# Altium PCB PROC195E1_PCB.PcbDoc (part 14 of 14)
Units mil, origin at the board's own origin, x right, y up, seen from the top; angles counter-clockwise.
Board outline 3110.24 x 2500 mil, 10 copper layers (Top Layer, L02_GND1, L03_SIG1, L04_GND2, L05_PWR1, L06_PWR2, L07_GND3, L08_SIG2, L09_GND4, Bottom Layer), stack 66.407 mil thick; 571 components, 538 nets, 6726 pads, 1286 vias.
Unrouted connection lines stored in the file: 4.
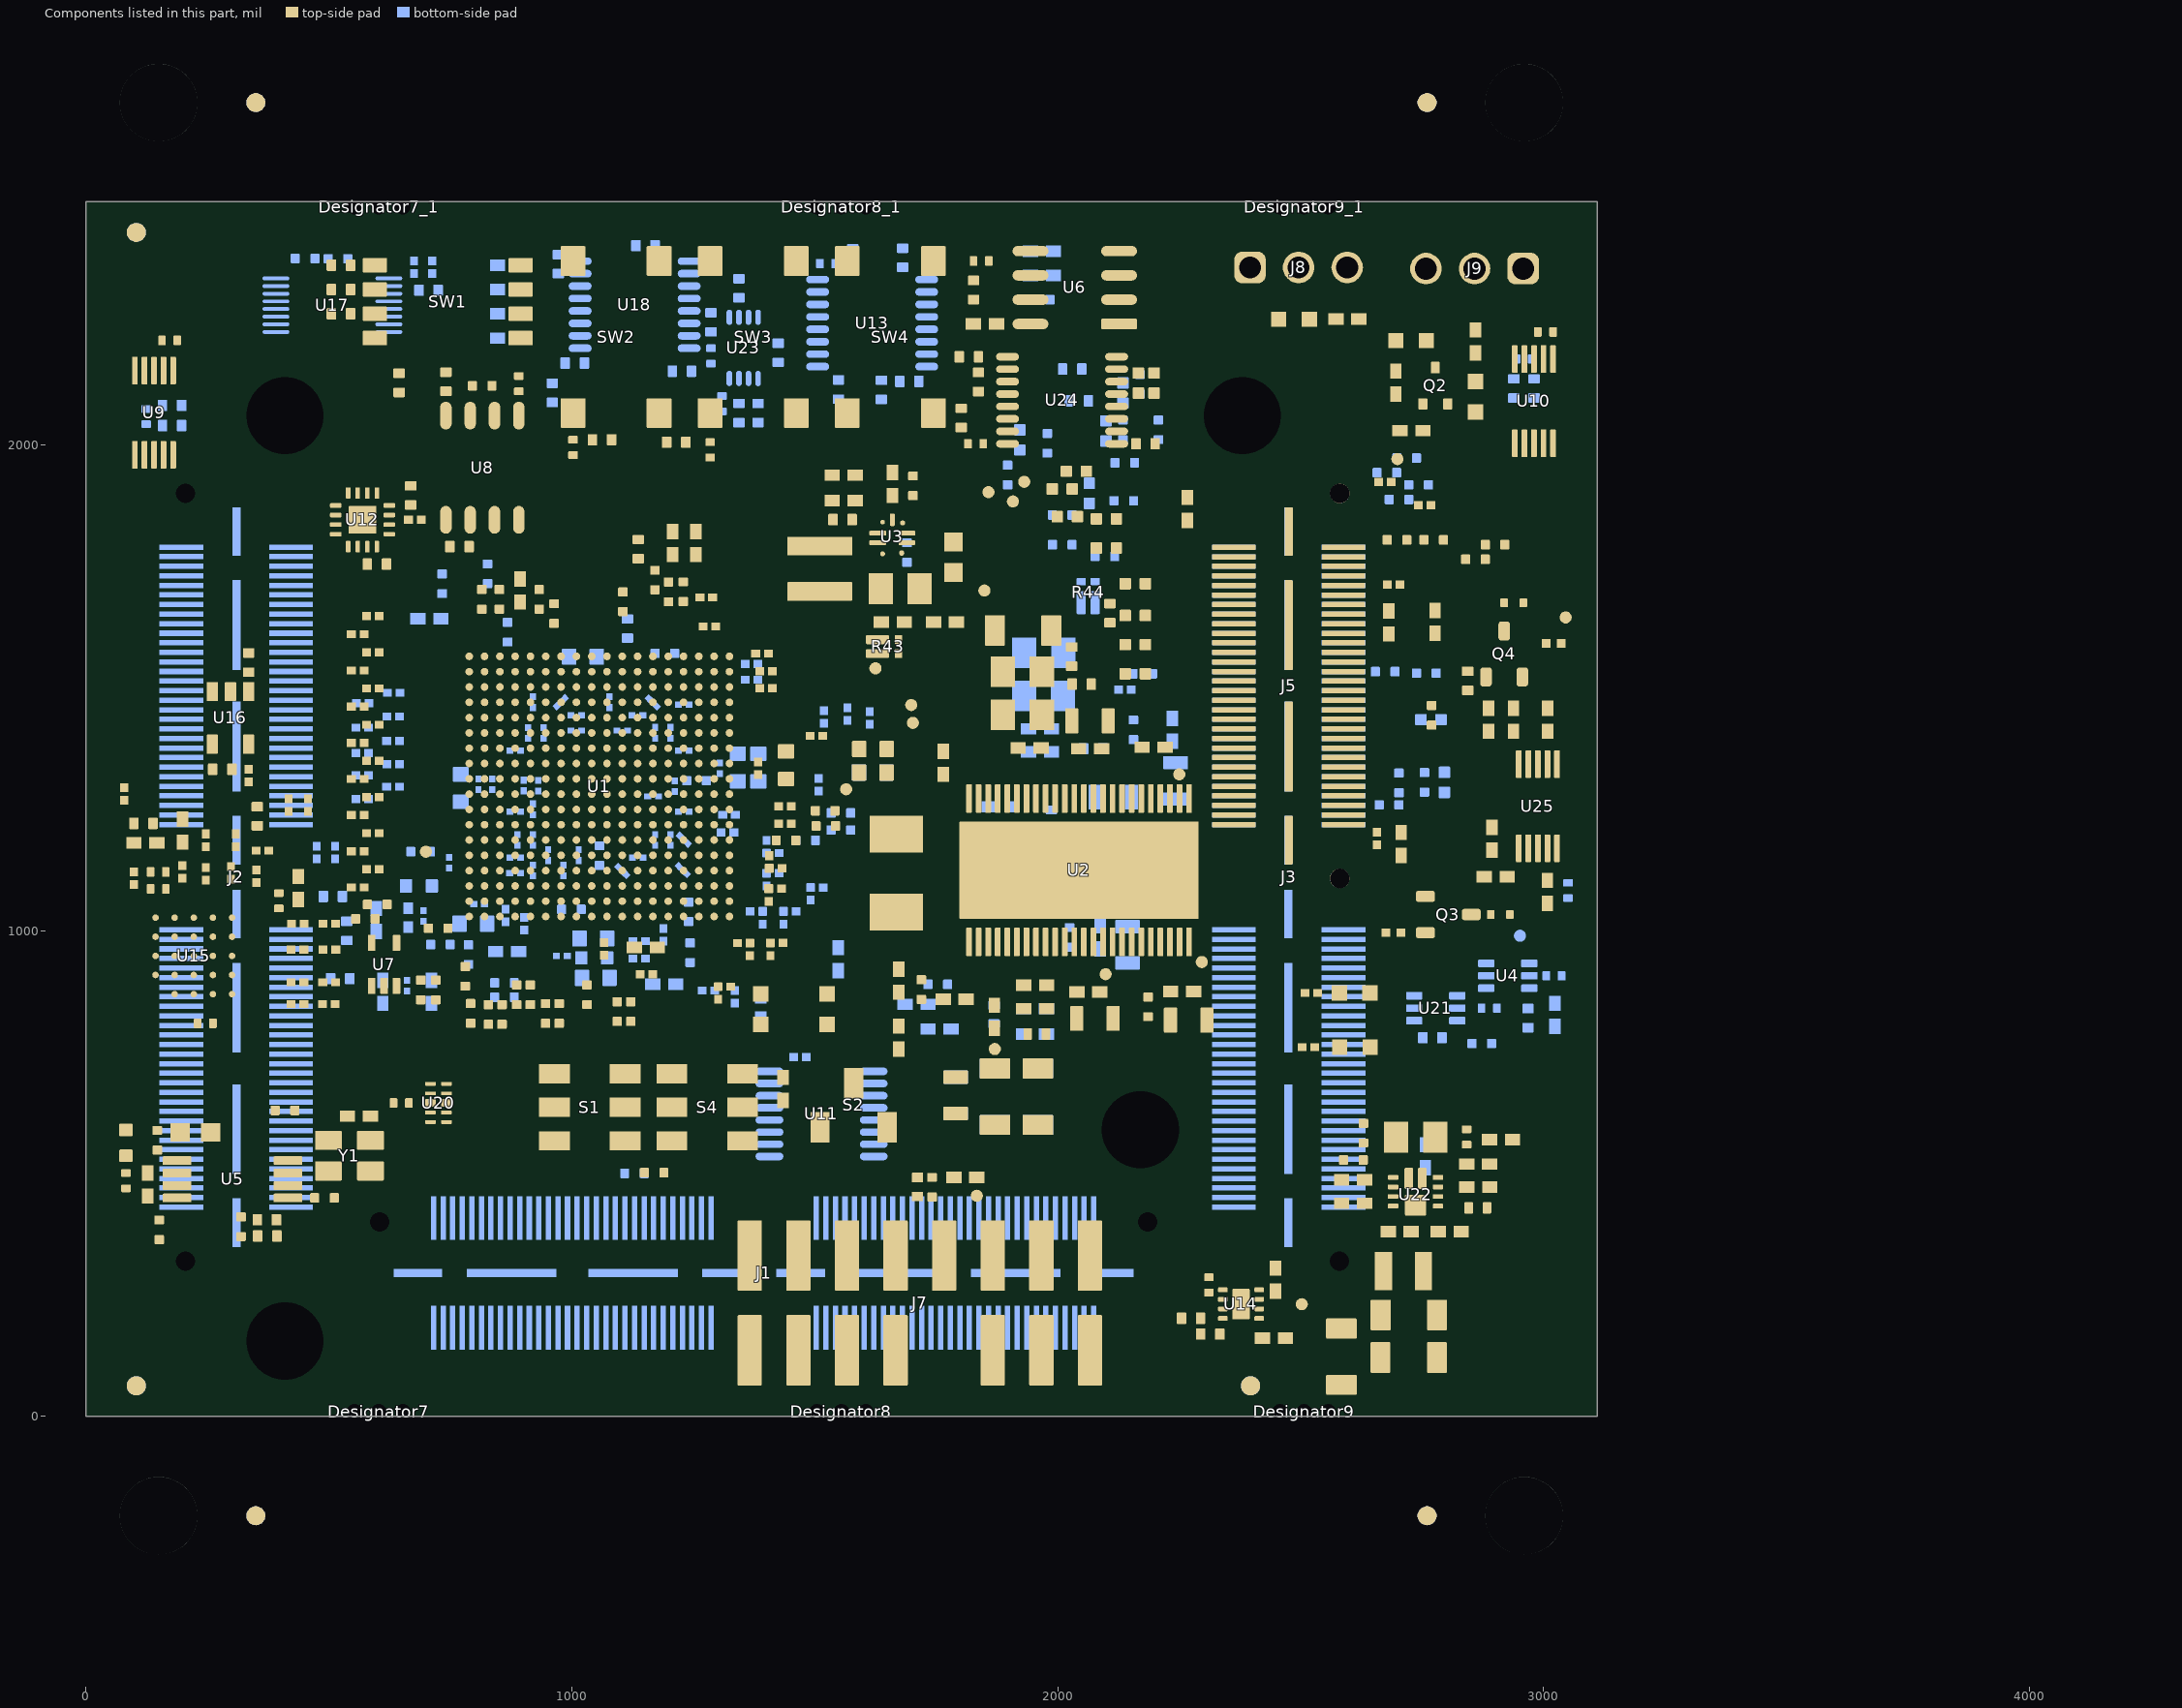
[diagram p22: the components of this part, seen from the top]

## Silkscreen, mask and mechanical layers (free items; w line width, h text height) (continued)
M10 Fab Notes:
  drawing of 181 lines, arcs and shapes, not listed
  text "DESIGN INFORMATION" at 11891.13,5008.92 h60
  text "3.2" at 12288,4885 h60
  text "MIN. TRACK WIDTH:" at 11246.57,4876.79 h60
  text "MIL" at 12497.57,4876.79 h60
  text "3.4" at 12290.75,4756.45 h60
  text "MIN. CLEARANCE:" at 11246.57,4752.67 h60
  text "MIL" at 12497.57,4752.67 h60
  text "MIN. VIA PAD SIZE:" at 11246.57,4628.54 h60
  text "18" at 12312.82,4628.54 h60
  text "MIL" at 12497.57,4628.54 h60
  text "0.05mm (2MIL)" at 11941.57,4498.64 h60
  text "MINIMUM ANNULAR RING" at 10917.34,4490.42 h60
  text "EXTERNAL" at 12649.57,4490.42 h60
  text "PER" at 11117.34,4380.29 h60
  text "IPC-D-275 CLASS 2 LEVEL C" at 11337.34,4380.29 h60
  text "MIL, HOLES" at 12825.57,4279.81 h60
  text "+/-" at 12433.11,4271.23 h60
  text "+/-" at 13287.11,4271.23 h60
  text "REGISTRATION TOLERANCES:" at 10917.34,4270.16 h60
  text "METAL" at 12117.11,4270.16 h60
  text "5" at 12693.31,4270.16 h60
  text "3" at 13526.31,4270.16 h60
  text "MIL" at 13642.57,4270.16 h60
  text "HOLE SIZE TOLERANCE (UNLESS OTHERWISE SPECIFIED):" at 10917.34,4171.85 h60
  text "+/-" at 13287.11,4168.97 h60
  text "3" at 13526.31,4167.91 h60
  text "MIL" at 13642.57,4167.91 h60
  text "MATERIAL:" at 10842.57,4030.26 h60
  text "FR-4 High Tg" at 11829.01,3901.74 h60
  text "X" at 11684.57,3893.75 h60
  text "FR-408" at 11263.57,3889.23 h60
  text "OTHER" at 12751.57,3889.23 h60
  text "70.4 MILS" at 13248.67,3756.2 h60
  text "62 MIL (1.6mm) +/-10%" at 11583.67,3746.2 h60
  text "X" at 12740,3740 h60
  text "THICKNESS:" at 10917.34,3737.98 h60
  text "OTHER" at 12868.57,3737.98 h60
  text "TOLERANCE:" at 10917.34,3599.67 h60
  text "X" at 11765.57,3599.67 h60
  text "ANSI IPC-6012 TYPE 3 CLASS 2" at 11943.58,3599.67 h60
  text "OTHER +/-" at 11943.57,3455.48 h60
  text "BOW & TWIST:" at 10917.34,3310.29 h60
  text "X" at 11765.57,3310.29 h60
  text "ANSI IPC-6012 TYPE 3 CLASS 2" at 11943.58,3310.29 h60
  text "SCALE : NTS" at 4511.09,3292.46 h80
  text "NOTES:" at 3394.07,3218.65 h60
  text "OTHER +/-" at 11943.57,3163.59 h60
  text "1. BOARD SHALL MEET THE REQUIREMENTS OF UL-796E WITH FLAMMABILITY RATING OF MINIMUM 94V-0. UL LOGO," at 3384.31,3046.2 h60
  text "DRILLING:" at 10842.57,3032.97 h60
  text "MANUFACTURER'S IDENTIFICATION AND DATE CODE LETTER SHALL BE RENDERED IN SILKSCREEN." at 3491.04,2947.21 h60
  text "NC_DRILL FILES" at 12603.57,2927.78 h60
  text "REFERENCE:" at 10917.34,2923.85 h60
  text "X" at 11574.57,2923.75 h60
  text "AS SHOWN" at 11752.57,2923.85 h60
  text "X" at 12475.57,2923.85 h60
  text "2. VENDOR MAY ADJUST SOLDERMASK WHEREVER SOLDERMASK PADS ARE THE SAME SIZE (1:1) AS PER THE MANUFACTURING CAPABILITIES" at 3377.33,2821.42 h60
  text "OTHER" at 12901.57,2781.59 h60
  text "PTH COPPER THICKNESS:" at 10917.01,2778.07 h60
  text "X" at 12056.25,2778.07 h60
  text "20-30 um" at 12184.24,2778.07 h60
  text "AND ALL OTHER SOLDER MASK PADS SHALL NOT BE MODIFIED, PROVIDED NO ADJACENT COPPER IS EXPOSED AND NO CONFLICT IS PRODUCED" at 3484.06,2722.43 h60
  text "BOARD FINISH:" at 10842.57,2630.47 h60
  text "WITH ANY STATED \"VIA TENTING/COVERING\" REQUIREMENTS." at 3484.06,2629.14 h60
  text "SILKSCREEN:" at 10997.79,2520.34 h60
  text "X" at 11955.57,2520.34 h60
  text "TOP" at 12072.57,2520.34 h60
  text "X" at 12465.57,2520.34 h60
  text "BOTTOM" at 12583.57,2520.34 h60
  text "3. MANUFACTURER'S IDENTIFICATION,DATECODE LETTER ALONG WITH UL94V-0 UL REGISTERED MATERIAL ID NUMBER SHALL BE SILKSCREENED ON SOLDER SIDE OF THE BOARD." at 3375.01,2493.62 h60
  text "SILKSCREEN COLOR:" at 10997.79,2365.15 h60
  text "X" at 11954.57,2365.15 h60
  text "WHITE" at 12072.57,2365.15 h60
  text "OTHER" at 12583.57,2365.15 h60
  text "4. LAYER TO LAYER REGISTRATION SHALL BE WITHIN +/-2 MIL." at 3381.01,2341.95 h60
  text "GREEN" at 12203.57,2221.71 h60
  text "OTHER" at 12821.57,2221.71 h60
  text "X" at 12085,2219 h60
  text "SOLDER RESIST COLOR:" at 10997.79,2214.84 h60
  text "5. REFER IMPEDANCE TABLE FOR IMPEDANCE CONTROL TRACES ON LAYER 1, 3, 5 , 8 & 10." at 3381.01,2176.08 h60
  text "X" at 12675.97,2069.73 h60
  text "MATTE" at 12203.57,2067.45 h60
  text "SEMI-GLOSS" at 12821.11,2066.82 h60
  text "6. ALL VIAS ARE TENTED ON BOTH SIDES UNLESS OTHERWISE SOLDER MASK OPENED IN GERBER." at 3381.01,2015.93 h60
  text "IMMERSION GOLD (ENIG)" at 11903.57,1894.68 h60
  text "ENEPIG" at 13241.11,1887.46 h60
  text "SURFACE FINISH:" at 10842.57,1886.46 h60
  text "X" at 11725.57,1886.46 h60
  text "IMM. TIN/SILVER OR EQUIV" at 11172.11,1749.15 h60
  text "OTHER" at 11193.57,1585.21 h60
  text "ARRAY/PANEL:" at 10842.57,1449.83 h60
  text "X" at 11730,1449 h60
  text "CUT AND TRIM PER M1 BOARD OUTLINE" at 11903.57,1441.61 h60
  text "N.C. ROUTE" at 11903.57,1305.64 h60
  text "V. SCORE" at 12769.57,1305.64 h60
  text "CERTIFICATION:" at 10842.57,1176.52 h60
  text "MATERIALS AND WORKMANSHIP FOR ALL PCBS" at 11567.57,1176.52 h60
  text "TO MEET OR EXCEED THE REQUIREMENTS OF:" at 11567.57,1082.45 h60
  text "X" at 11205.08,953.82 h60
  text "ANSI IPC-A-600F CLASS ->" at 11333.07,953.82 h60
  text "X" at 12981.08,953.82 h60
  text "2" at 13091.07,953.82 h60
  text "1" at 12776.07,952.33 h60
  text "3" at 13445.07,952.33 h60
  text "X" at 12017.08,806.14 h60
  text "RoHS" at 12145.07,806.14 h60
  text "OTHER" at 12789.47,806.14 h60
  text "PER ORDER" at 13186.53,806.14 h60
  text "ALL BOARDS MUST MEET OR EXCEED UL94-V0 REQUIREMENTS." at 10870.11,652.31 h60
  text "PCB MUST BEAR THE UL94V-0 UL REGISTERED MATERIAL ID NUMBER" at 10870.11,536.25 h60
  text "ADDITIONAL REQUIREMENTS:" at 10842.57,366.82 h60
  text "REQUIRED" at 12624.57,245.36 h60
  text "BARE BOARD ELEC. TEST:" at 10857.34,242.51 h60
  text "NONE" at 12163.07,242.51 h60
  text "X" at 13099.11,242.74 h60
  text "PER ORDER" at 13216.57,242.51 h60
  text "OUTER LAYERS 6 MIL WIDE, 6 MIL SPACE / TRACES REQUIRE 100 OHM DIFFERENTIAL IMPEDANCE" at 11094.18,-59.19 h60
  text "INNER LAYERS 5 MIL WIDE, 7 MIL SPACE / TRACES REQUIRE 100 OHM DIFFERENTIAL IMPEDANCE" at 11064.18,-244.19 h60
  text "OUTER LAYERS 6.1 MIL WIDE, 6 MIL SPACE / TRACES REQUIRE 90 OHM DIFFERENTIAL IMPEDANCE" at 11076.5,-430.04 h60
  text ".Layer_Name" at 35,-2376 h60
M11 Gerber Information:
  lines w10: -782.89,-2417.42 5817.11,-2417.42 ; -782.89,-2214.09 5819.11,-2214.09 ; -782.89,-2010.76 -782.89,-2620.76 3222.11,-2620.76 5819.11,-2620.76 5819.11,-2010.76 -782.39,-2010.76 -782.39,-2620.76 793.11,-2620.76 ; 1682.11,-2620.76 1682.11,-2010.76 ; 2949.11,-2214.09 2949.11,-2010.76 ; 3789.11,-2214.09 3789.11,-2010.76 ; 4411.11,-2627.26 4411.11,-2424.42
  text "ALL ARTWORK VIEWED FROM TOP SIDE" at -719.39,-2142.92 h60
  text "BOARD #:" at 1757.11,-2142.92 h60
  text ".PRJ_Number" at 2302.61,-2142.92 h60
  text "REV:" at 3147.11,-2142.92 h60
  text ".PCB_Rev" at 3438.61,-2142.92 h60
  text "SVN REV:" at 3985.11,-2142.92 h60
  text ".VersionControl_RevNumber" at 4491.11,-2142.92 h60
  text "LAYER NAME =" at -719.39,-2345.75 h60
  text "TID #:" at 1757.11,-2346.26 h60
  text ".TID" at 2302.61,-2346.26 h60
  text "PLOT NAME =" at -719.39,-2551.59 h60
  text ".plot_File_Name" at 86.11,-2551.59 h60
  text "GENERATED    :" at 1759.11,-2551.59 h60
  text ".Print_Date" at 2628.61,-2551.59 h60
  text ".Print_Time" at 3357.61,-2551.59 h60
  text "TEXAS INSTRUMENTS" at 4622.11,-2551.59 h60
M12 Stackup:
  drawing of 743 lines, arcs and shapes, not listed
  text "IMPEDANCE TABLE :" at 8653.95,6316.23 h80
  text "LAYER" at 8194.22,6126.58 h70
  text "TRACE WIDTH" at 8481.42,6125.73 h70
  text "SPACING" at 8966.42,6125.73 h70
  text "IMPEDANCE +/- 10%" at 9301.42,6125.73 h70
  text "REFERENCE LAYER" at 10026.42,6125.73 h70
  text "-" at 9089,5955 h65
  text "LAYER-2 (GND LAYER)" at 9987.83,5949.75 h65
  text "5.8 MILS" at 8580.1,5944.75 h65
  text "50 OHM" at 9464.3,5945 h65
  text "TOP" at 8219,5940 h70
  text "100 OHM" at 9464.3,5775.87 h65
  text "4.25 MILS" at 8580.1,5770.87 h65
  text "LAYER-2 (GND LAYER)" at 9987.83,5767.55 h65
  text "7.15 MILS" at 8993.35,5765 h65
  text "TOP" at 8224,5750 h70
  text "90 OHM" at 9464.3,5581.55 h65
  text "LAYER-2 (GND LAYER)" at 9987.83,5581.55 h65
  text "4.4 MILS" at 8993.35,5580 h65
  text "4.2 MILS" at 8580.1,5575.87 h65
  text "TOP" at 8224,5575 h60
  text "50 OHM" at 9464.3,5390.87 h65
  text "L3" at 8259,5390 h60
  text "-" at 9094,5390 h65
  text "3.6  MILS" at 8580.1,5385.87 h65
  text "LAYER-2 / LAYER-4" at 9987.83,5381.52 h65
  text "100 OHM" at 9464.3,5215.87 h65
  text "L3" at 8259,5215 h60
  text "3.2  MILS" at 8580.1,5210.87 h65
  text "7.5 MILS" at 8993.35,5210 h65
  text "LAYER-2 / LAYER-4" at 9987.83,5206.52 h65
  text "-" at 9083,5038 h65
  text "3.6  MILS" at 8572,5034 h65
  text "50 OHM" at 9473,5033 h65
  text "LAYER-7/LAYER-9" at 10002.83,5032.26 h65
  text "L8" at 8259,5028 h60
  text "3.7  MILS" at 8581,4867 h65
  text "90 OHM" at 9478,4863 h65
  text "LAYER-7/LAYER-9" at 10007.83,4862.26 h65
  text "L8" at 8264,4858 h60
  text "6 MILS" at 8998,4858 h65
  text "3.2 MILS" at 8575,4691 h65
  text "7.5 MILS" at 8993.35,4683.87 h65
  text "LAYER-7/LAYER-9" at 10002.83,4682.26 h65
  text "L8" at 8259,4678 h60
  text "100 OHM" at 9468,4678 h65
  text "-" at 9089,4524 h65
  text "LAYER-9(GND LAYER)" at 10002.83,4515 h65
  text "5.8 MILS" at 8580.1,4513.75 h65
  text "50 OHM" at 9464.3,4514 h65
  text "BOTTOM" at 8181.67,4502.48 h60
  text "100 OHM" at 9464.3,4344.87 h65
  text "4.25 MILS" at 8580.1,4339.87 h65
  text "LAYER-9(GND LAYER)" at 10002.83,4335 h65
  text "7.15 MILS" at 8993.35,4334 h65
  text "BOTTOM" at 8184.67,4326.48 h60
  text "LAYER-9(GND LAYER)" at 10002.83,4160 h65
  text "BOTTOM" at 8184.67,4155.25 h60
  text "90 OHM" at 9464.3,4150.55 h65
  text "4.4 MILS" at 8993.35,4149 h65
  text "4.2 MILS" at 8580.1,4144.87 h65
  text "Layer" at 5162.64,1463.32 h60
  text "Name" at 5572.55,1463.32 h60
  text "Material" at 6502.3,1463.32 h60
  text "Thickness" at 7761.93,1463.32 h60
  text "Constant" at 8411.77,1463.32 h60
  text "Board Layer Stack" at 8981.63,1463.32 h60
  text "Top Overlay" at 5572.55,1343.32 h60
  text "Top Solder" at 5572.55,1223.32 h60
  text "Solder Resist" at 6502.3,1223.32 h60
  text "2.00mil" at 7761.93,1223.32 h60
  text "3.9" at 8411.77,1223.32 h60
  text "1" at 5162.64,1103.32 h60
  text "Top Layer" at 5572.55,1103.32 h60
  text "1.85mil" at 7761.93,1103.32 h60
  text "Dielectric 2" at 5572.55,983.32 h60
  text "FR-4" at 6502.3,983.32 h60
  text "3.70mil" at 7761.93,983.32 h60
  text "3.79" at 8411.77,983.32 h60
  text "2" at 5162.64,863.32 h60
  text "L02_GND1" at 5572.55,863.32 h60
  text "1.26mil" at 7761.93,863.32 h60
  text "Dielectric 4" at 5572.55,743.32 h60
  text "FR-4" at 6502.3,743.32 h60
  text "4.00mil" at 7761.93,743.32 h60
  text "4.4" at 8411.77,743.32 h60
  text "3" at 5162.64,623.32 h60
  text "L03_SIG1" at 5572.55,623.32 h60
  text "1.26mil" at 7761.93,623.32 h60
  text "Dielectric 6" at 5572.55,503.32 h60
  text "FR-4" at 6502.3,503.32 h60
  text "6.59mil" at 7761.93,503.32 h60
  text "4.13" at 8411.77,503.32 h60
  text "4" at 5162.64,383.32 h60
  text "L04_GND2" at 5572.55,383.32 h60
  text "CF-001" at 6502.3,383.32 h60
  text "1.26mil" at 7761.93,383.32 h60
  text "Dielectric 8" at 5572.55,263.32 h60
  text "FR-4" at 6502.3,263.32 h60
  text "5.00mil" at 7761.93,263.32 h60
  text "4.21" at 8411.77,263.32 h60
  text "5" at 5162.64,143.32 h60
  text "L05_PWR1" at 5572.55,143.32 h60
  text "CF-004" at 6502.3,143.32 h60
  text "1.26mil" at 7761.93,143.32 h60
  text "Dielectric 10" at 5572.55,23.32 h60
  text "PP-006" at 6502.3,23.32 h60
  text "6.09mil" at 7761.93,23.32 h60
  text "4.13" at 8411.77,23.32 h60
  text "Dielectric 1" at 5572.55,-96.68 h60
  text "Composite dielectric" at 6502.3,-96.68 h60
  text "1.88mil" at 7761.93,-96.68 h60
  text "4.13" at 8411.77,-96.68 h60
  text "Dielectric 11" at 5572.55,-216.68 h60
  text "PP-006" at 6502.3,-216.68 h60
  text "6.09mil" at 7761.93,-216.68 h60
  text "4.13" at 8411.77,-216.68 h60
  text "6" at 5162.64,-336.68 h60
  text "L06_PWR2" at 5572.55,-336.68 h60
  text "CF-004" at 6502.3,-336.68 h60
  text "1.26mil" at 7761.93,-336.68 h60
  text "Dielectric 9" at 5572.55,-456.68 h60
  text "FR-4" at 6502.3,-456.68 h60
  text "5.00mil" at 7761.93,-456.68 h60
  text "4.21" at 8411.77,-456.68 h60
  text "7" at 5162.64,-576.68 h60
  text "L07_GND3" at 5572.55,-576.68 h60
  text "CF-001" at 6502.3,-576.68 h60
  text "1.26mil" at 7761.93,-576.68 h60
  text "Dielectric 7" at 5572.55,-696.68 h60
  text "FR-4" at 6502.3,-696.68 h60
  text "6.59mil" at 7761.93,-696.68 h60
  text "4.13" at 8411.77,-696.68 h60
  text "8" at 5162.64,-816.68 h60
  text "L08_SIG2" at 5572.55,-816.68 h60
  text "1.26mil" at 7761.93,-816.68 h60
  text "Dielectric 5" at 5572.55,-936.68 h60
  text "FR-4" at 6502.3,-936.68 h60
  text "4.00mil" at 7761.93,-936.68 h60
  text "4.4" at 8411.77,-936.68 h60
  text "9" at 5162.64,-1056.68 h60
  text "L09_GND4" at 5572.55,-1056.68 h60
  text "1.26mil" at 7761.93,-1056.68 h60
  text "Dielectric 3" at 5572.55,-1176.68 h60
  text "FR-4" at 6502.3,-1176.68 h60
  text "3.70mil" at 7761.93,-1176.68 h60
  text "3.79" at 8411.77,-1176.68 h60
  text "10" at 5162.64,-1296.68 h60
  text "Bottom Layer" at 5572.55,-1296.68 h60
  text "1.85mil" at 7761.93,-1296.68 h60
  text "Bottom Solder" at 5572.55,-1416.68 h60
  text "Solder Resist" at 6502.3,-1416.68 h60
  text "2.00mil" at 7761.93,-1416.68 h60
  text "3.9" at 8411.77,-1416.68 h60
  text "Bottom Overlay" at 5572.55,-1536.68 h60
  text ".Layer_Name" at 31,-2369 h60
Drill Drawing:
  circle w10: c-549.48,5963.42 r19.95
  circle w10: c-549.48,5963.42 r33.24
  circle w10: c-549.48,4916.31 r33.24
  lines w10: -582.72,5065.89 -549.48,5032.65 -516.24,5065.89 -549.48,5099.13 -582.72,5065.89 ; -582.72,5198.86 -566.1,5198.86 -549.48,5182.24 -532.86,5198.86 -516.24,5198.86 -532.86,5215.48 -516.24,5232.1 -532.86,5232.1 -549.48,5248.72 -566.1,5232.1 -582.72,5232.1 -566.1,5215.48 -582.72,5198.86 ; -582.72,5331.83 -582.72,5348.45 -566.1,5365.07 -582.72,5381.69 -582.72,5398.31 -566.1,5398.31 -549.48,5381.69 -532.86,5398.31 -516.24,5398.31 -516.24,5381.69 -532.86,5365.07 -516.24,5348.45 -516.24,5331.83 -532.86,5331.83 -549.48,5348.45 -566.1,5331.83 -582.72,5331.83 ; -582.72,5481.41 -549.48,5498.03 -516.24,5481.41 -532.86,5514.65 -516.24,5547.9 -549.48,5531.28 -582.72,5547.9 -566.1,5514.65 -582.72,5481.41 ; -582.72,5631 -516.24,5631 -516.24,5697.48 -582.72,5697.48 -582.72,5631 ; -582.72,5780.59 -516.24,5780.59 -516.24,5847.07 -582.72,5847.07 -582.72,5780.59 ; -569.43,5205.51 -559.45,5205.51 -549.48,5195.54 -539.51,5205.51 -529.54,5205.51 -539.51,5215.48 -529.54,5225.45 -539.51,5225.45 -549.48,5235.43 -559.45,5225.45 -569.43,5225.45 -559.45,5215.48 -569.43,5205.51 ; -569.43,5644.3 -529.54,5644.3 -529.54,5684.19 -569.43,5684.19 -569.43,5644.3
  lines w15: -642.36,4838.19 8002.05,4838.19 ; -642.36,6034.89 8002.05,6034.89 ; -92.91,4688.6 -92.91,6184.47 ; 555.18,4688.6 555.18,6184.47 ; 1701.74,4688.6 1701.74,6184.47 ; 2565.2,4688.6 2565.2,6184.47 ; 3069.77,4688.6 3069.77,6184.47 ; 3801.64,4688.6 3801.64,6184.47 ; 5297.12,4688.6 5297.12,6184.47 ; 6627.15,4688.6 6627.15,6184.47 ; -642.36,4688.6 8002.05,4688.6 8002.05,6184.47 -642.36,6184.47 -642.36,4688.6
  text "Symbol" at -552.61,6079.76 h71.8
  text "Count" at -48.03,6079.76 h71.8
  text "Hole Size" at 600.06,6079.76 h71.8
  text "Hole Length" at 1746.61,6079.76 h71.8
  text "Plated" at 2610.08,6079.76 h71.8
  text "Hole Type" at 3114.65,6079.76 h71.8
  text "Drill Layer Pair" at 3846.52,6079.76 h71.8
  text "Hole Tolerance (+)" at 5342,6079.76 h71.8
  text "Hole Tolerance (-)" at 6672.03,6079.76 h71.8
  text "60" at -48.03,5930.17 h59.83
  text "7.87mil (0.200mm)" at 600.06,5930.17 h59.83
  text "-" at 1746.61,5930.17 h59.83
  text "PTH" at 2610.08,5930.17 h59.83
  text "Round" at 3114.65,5930.17 h59.83
  text "Top Layer - Bottom Layer" at 3846.52,5930.17 h59.83
  text "3.00mil (0.076mm)" at 5342,5930.17 h59.83
  text "3.00mil (0.076mm)" at 6672.03,5930.17 h59.83
  text "1226" at -48.03,5780.59 h59.83
  text "8.00mil (0.203mm)" at 600.06,5780.59 h59.83
  text "-" at 1746.61,5780.59 h59.83
  text "PTH" at 2610.08,5780.59 h59.83
  text "Round" at 3114.65,5780.59 h59.83
  text "Top Layer - Bottom Layer" at 3846.52,5780.59 h59.83
  text "3.00mil (0.076mm)" at 5342,5780.59 h59.83
  text "3.00mil (0.076mm)" at 6672.03,5780.59 h59.83
  text "18" at -48.03,5631 h59.83
  text "32.00mil (0.813mm)" at 600.06,5631 h59.83
  text "-" at 1746.61,5631 h59.83
  text "NPTH" at 2610.08,5631 h59.83
  text "Round" at 3114.65,5631 h59.83
  text "Top Layer - Bottom Layer" at 3846.52,5631 h59.83
  text "3.00mil (0.076mm)" at 5342,5631 h59.83
  text "3.00mil (0.076mm)" at 6672.03,5631 h59.83
  text "6" at -48.03,5481.41 h59.83
  text "40.00mil (1.016mm)" at 600.06,5481.41 h59.83
  text "-" at 1746.61,5481.41 h59.83
  text "NPTH" at 2610.08,5481.41 h59.83
  text "Round" at 3114.65,5481.41 h59.83
  text "Top Layer - Bottom Layer" at 3846.52,5481.41 h59.83
  text "3.00mil (0.076mm)" at 5342,5481.41 h59.83
  text "3.00mil (0.076mm)" at 6672.03,5481.41 h59.83
  text "2" at -48.03,5331.83 h59.83
  text "40.16mil (1.020mm)" at 600.06,5331.83 h59.83
  text "-" at 1746.61,5331.83 h59.83
  text "NPTH" at 2610.08,5331.83 h59.83
  text "Round" at 3114.65,5331.83 h59.83
  text "Top Layer - Bottom Layer" at 3846.52,5331.83 h59.83
  text "2.00mil (0.051mm)" at 5342,5331.83 h59.83
  text "2.00mil (0.051mm)" at 6672.03,5331.83 h59.83
  text "6" at -48.03,5182.24 h59.83
  text "45.28mil (1.150mm)" at 600.06,5182.24 h59.83
  text "-" at 1746.61,5182.24 h59.83
  text "PTH" at 2610.08,5182.24 h59.83
  text "Round" at 3114.65,5182.24 h59.83
  text "Top Layer - Bottom Layer" at 3846.52,5182.24 h59.83
  text "3.00mil (0.076mm)" at 5342,5182.24 h59.83
  text "3.00mil (0.076mm)" at 6672.03,5182.24 h59.83
  text "4" at -48.03,5032.65 h59.83
  text "159.00mil (4.039mm)" at 600.06,5032.65 h59.83
  text "-" at 1746.61,5032.65 h59.83
  text "NPTH" at 2610.08,5032.65 h59.83
  text "Round" at 3114.65,5032.65 h59.83
  text "Top Layer - Bottom Layer" at 3846.52,5032.65 h59.83
  text "3.00mil (0.076mm)" at 5342,5032.65 h59.83
  text "3.00mil (0.076mm)" at 6672.03,5032.65 h59.83
  text "4" at -48.03,4883.06 h59.83
  text "160.00mil (4.064mm)" at 600.06,4883.06 h59.83
  text "-" at 1746.61,4883.06 h59.83
  text "NPTH" at 2610.08,4883.06 h59.83
  text "Round" at 3114.65,4883.06 h59.83
  text "Top Layer - Bottom Layer" at 3846.52,4883.06 h59.83
  text "2.00mil (0.051mm)" at 5342,4883.06 h59.83
  text "2.00mil (0.051mm)" at 6672.03,4883.06 h59.83
  text "1326 Total" at -48.03,4733.48 h59.83
  text ".Layer_Name" at 86.11,-2345.75 h60
M17 Embedded Cavity:
  text ".Layer_Name" at 74.33,-2325.71 h60
M18 Embedded Assembly:
  text ".Layer_Name" at 74.33,-2325.71 h60
M19 Embedded Keepout:
  text ".Layer_Name" at 34,-2373 h60
DXF_MCU131A_SOM_EVM_BOTTOM:
  drawing of 4604 lines, arcs and shapes, not listed
Sheet:
  drawing of 57 lines, arcs and shapes, not listed
  text "1" at 248.94,6549.24 h70
  text "2" at 2744.61,6549.24 h70
  text "3" at 5233.95,6549.24 h70
  text "4" at 7740.62,6549.24 h70
  text "5" at 10239.61,6549.24 h70
  text "6" at 12744.61,6549.24 h70
  text "A" at -907.39,5406.24 h70
  text "A" at 13892.61,5406.24 h70
  text "B" at -907.39,3026.24 h70
  text "B" at 13892.61,3026.24 h70
  text "C" at -907.39,651.24 h70
  text "C" at 13892.61,651.24 h70
  text "PROJECT TITLE:" at 10852.61,-1209.76 h45
  text ".PRJ_Title" at 10902.61,-1343.08 h70
  text "DESIGNED FOR:" at 10852.61,-1510.76 h45
  text ".PRJ_Customer" at 10902.61,-1650.76 h70
  text "D" at -907.39,-1718.76 h70
  text "D" at 13892.61,-1718.76 h70
  text "FILE NAME:" at 10852.61,-1810.76 h45
  text ".PCB_File_Name_No_Path" at 10902.61,-1930.76 h70
  text "Texas Instruments (TI) and/or its licensors do not warrant the accuracy or completeness of this specification" at 5883.11,-2092.6 h45
  text "ENGINEER:" at 10852.61,-2100.76 h45
  text "LAYOUT BY:" at 12357.61,-2100.76 h45
  text "or any information contained therein. TI and/or its licensors do not warrant that this design will meet" at 5838.12,-2205.26 h45
  text ".PRJ_Engineer" at 10902.61,-2255.75 h70
  text ".PCB_Layout" at 12408.11,-2255.75 h70
  text "the specifications, will be suitable for your application or fit for any particular purpose, or will operate in" at 5838.12,-2317.93 h45
  text ".Layer_Name" at 32,-2379 h60
  text "ALTIUM DESIGNER VERSION:" at 12357.61,-2410.76 h45
  text "an implementation. TI and/or its licensors do not warrant that the design is production worthy. You should" at 5838.12,-2430.59 h45
  text "completely validate and test your design implementation to confirm the system functionality for your application." at 5883.11,-2543.26 h45
  text ".print_Scale" at 10902.61,-2544.08 h70
  text ".Application_BuildNumber" at 12408.11,-2544.08 h70
  text "1" at 248.94,-2750.76 h70
  text "2" at 2744.61,-2750.76 h70
  text "3" at 5233.95,-2750.76 h70
  text "4" at 7740.62,-2750.76 h70
  text "5" at 10239.61,-2750.76 h70
  text "6" at 12744.61,-2750.76 h70
DXF_MCU134A_BASE_BRD_TOP:
  drawing of 3299 lines, arcs and shapes, not listed
  text "J7" at 3101.18,2148.51 h55
  text "MH3" at 2191.68,2083.5 h25
  text "MH2" at 545.68,2075.5 h25
  text "2" at 2110,2070 h40
  text "J2" at 194.02,1924.01 h60
  text "J3" at 2471.07,1916.8 h60
  text "J4" at 2205.02,1915.01 h60
  text "R29" at 2717.68,1903.5 h25
  text "R8" at 2831.5,1903.17 h25 r90
  text "R7" at 2892.5,1900.17 h25 r90
  text "P1" at 3202,1847 h55
  text "1" at 480,1845 h40
  text "ECAT1" at 3275.28,1841.1 h55
  text "2" at 125,1830 h40
  text "R31" at 2660.5,1807.84 h25 r90
  text "R3" at 2919.17,1789.5 h25
  text "1" at 2115,1720 h40
  text "R24" at 2663.5,1694.68 h25 r90
  text "R23" at 3034.68,1648.5 h25
  text "R16" at 2774.76,1636.5 h25
  text "R15" at 2686.76,1634.5 h25
  text "R17" at 2893.5,1603.76 h25 r90
  text "U1" at 2668.34,1577.5 h25
  text "R4" at 2958.17,1574.5 h25
  text "U2" at 2966.17,1521.5 h25
  text "C13" at 2947.76,1459.5 h25
  text "PHY1" at 2695,1435 h55 r90
  text "R11" at 2652.93,1377.5 h25
  text "C11" at 3038.93,1294.5 h25
  text "R1" at 3585.5,1272.34 h25 r90
  text "R19" at 3535.5,1244.76 h25 r90
  text "J5" at 3066,1244 h25
  text "R26" at 3428.5,1243.68 h25 r90
  text "R27" at 3486.5,1243.68 h25 r90
  text "R22" at 3632.5,1236.68 h25 r90
  text "R10" at 2737.5,1163.76 h25 r90
  text "D1" at 2778.34,1142.5 h25
  text "R90" at 3036.68,1132.5 h25
  text "D2" at 2774.17,1087.5 h25
  text "R93" at 3036.68,1087.5 h25
  text "R35" at 2941.68,1007.5 h25
  text "R86" at 3085.5,995.68 h25 r90
  text "R84" at 3130.5,995.68 h25 r90
  text "R63" at 3173.5,995.68 h25 r90
  text "R62" at 3217.5,995.68 h25 r90
  text "TP4" at 3356.68,990.01 h40
  text "R78" at 3186.5,853.68 h25 r90
  text "R70" at 3229.5,853.68 h25 r90
  text "R71" at 3272.5,853.68 h25 r90
  text "R72" at 3314.5,853.68 h25 r90
  text "R58" at 3355.5,853.68 h25 r90
  text "R32" at 3027.68,747.5 h25
  text "C80" at 792.5,736.68 h25 r90
  text "C67" at 867.5,736.68 h25 r90
  text "C84" at 932.5,736.68 h25 r90
  text "C71" at 1000.5,736.68 h25 r90
  text "C85" at 1070.5,736.68 h25 r90
  text "C72" at 1135.5,736.68 h25 r90
  text "C74" at 1202.5,736.68 h25 r90
  text "C73" at 1267.5,736.68 h25 r90
  text "C78" at 527.5,731.68 h25 r90
  text "C65" at 597.5,731.68 h25 r90
  text "C79" at 667.5,731.68 h25 r90
  text "C66" at 727.5,731.68 h25 r90
  text "MH1" at 2135.84,712.5 h25
  text "U3" at 2797.17,661.5 h25
  text "R59" at 2947.68,620.5 h25
  text "R36" at 1752.68,575.5 h25
  text "C20" at 1894.68,571.5 h25
  text "U6" at 2997.5,534.17 h25 r90
  text "PHY0" at 2690,480 h55 r90
  text "C21" at 1810.84,471.5 h25
  text "2" at 2112,444 h25
  text "C15" at 2877.53,368.99 h25
  text "1" at 2285,365 h40
  text "2" at 2625,355 h40
  text "C16" at 3039.76,314.5 h25
  text "MH4" at 217.68,259.5 h25
  text "R66" at 2693.5,204.68 h25 r90
  text "R65" at 2740.5,204.68 h25 r90
  text "R80" at 2789.5,166.68 h25 r90
  text "J11" at 3177.93,163.5 h25
  text "R81" at 2851.26,159.52 h25 r90
  text "TP1" at 2499.35,155.01 h40
  text "R82" at 2904.1,155.36 h25 r90
  text "R56" at 2951.74,155.36 h25 r90
  text "R55" at 3005.8,142.7 h25 r90
  text "1" at 2094,89 h25
  text "R113" at 1150.35,87.5 h25
  text "R100" at 560.26,85.5 h25
  text "R110" at 814.35,77.5 h25
  text "R102" at 691.26,74.5 h25
  text "TP2" at 2366.62,52.35 h40
  text "TP3" at 2287.99,23.68 h40 r90
  text "J1" at 1475.34,16.38 h60
  text "ECAT0" at 3440,10 h55
  text "P0" at 3335,5 h55
  text "R98" at 386.68,2.5 h25
  text "R97" at 298.68,1.5 h25
  text "R99" at 497.5,-13.32 h25 r90
  text "R114" at 1313.5,-12.65 h25 r90
  text "R111" at 1013.7,-22.86 h25 r90
  text "C22" at 2281.68,-57.5 h25
  text "U4" at 524.17,-72.5 h25
  text "U5" at 759.17,-77.5 h25
  text "R101" at 628.43,-79.5 h25
  text "C24" at 2121.68,-105.5 h25
  text "C35" at 631.68,-122.5 h25
  text "R112" at 1096.89,-129.47 h25 r90
  text "R109" at 870.33,-130.93 h25 r90
  text "SHLD_GND" at 3815,-145 h55
  text "C37" at 1123.36,-160.3 h25
  text "C26" at 2120.68,-161.5 h25
  text "C25" at 912.9,-169.62 h25 r90
  text "C23" at 2280.68,-220.5 h25
  text "C34" at 476.68,-222.5 h25
  text "U9" at 1004.76,-222.56 h25
  text "R45" at 382.68,-226.5 h25
  text "EC2" at 3787.82,-245.67 h25
  text "EC1" at 418.84,-283.5 h25
  text "M1 Board Outline" at 25.19,-2291.02 h60
  text "Top Overlay" at 19.19,-2367.03 h60
  text "Top Solder" at 19.3,-2368.03 h60
  text "Top Solder" at 19.3,-2368.03 h60
  text "Bottom Solder" at -975.77,-5469.5 h60

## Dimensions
0,2854.34 to 0,-354.34 on M2 Board Dimensions
0,2500 to 0,0 on M2 Board Dimensions
3110.24,2500 to 0,2500 on M2 Board Dimensions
